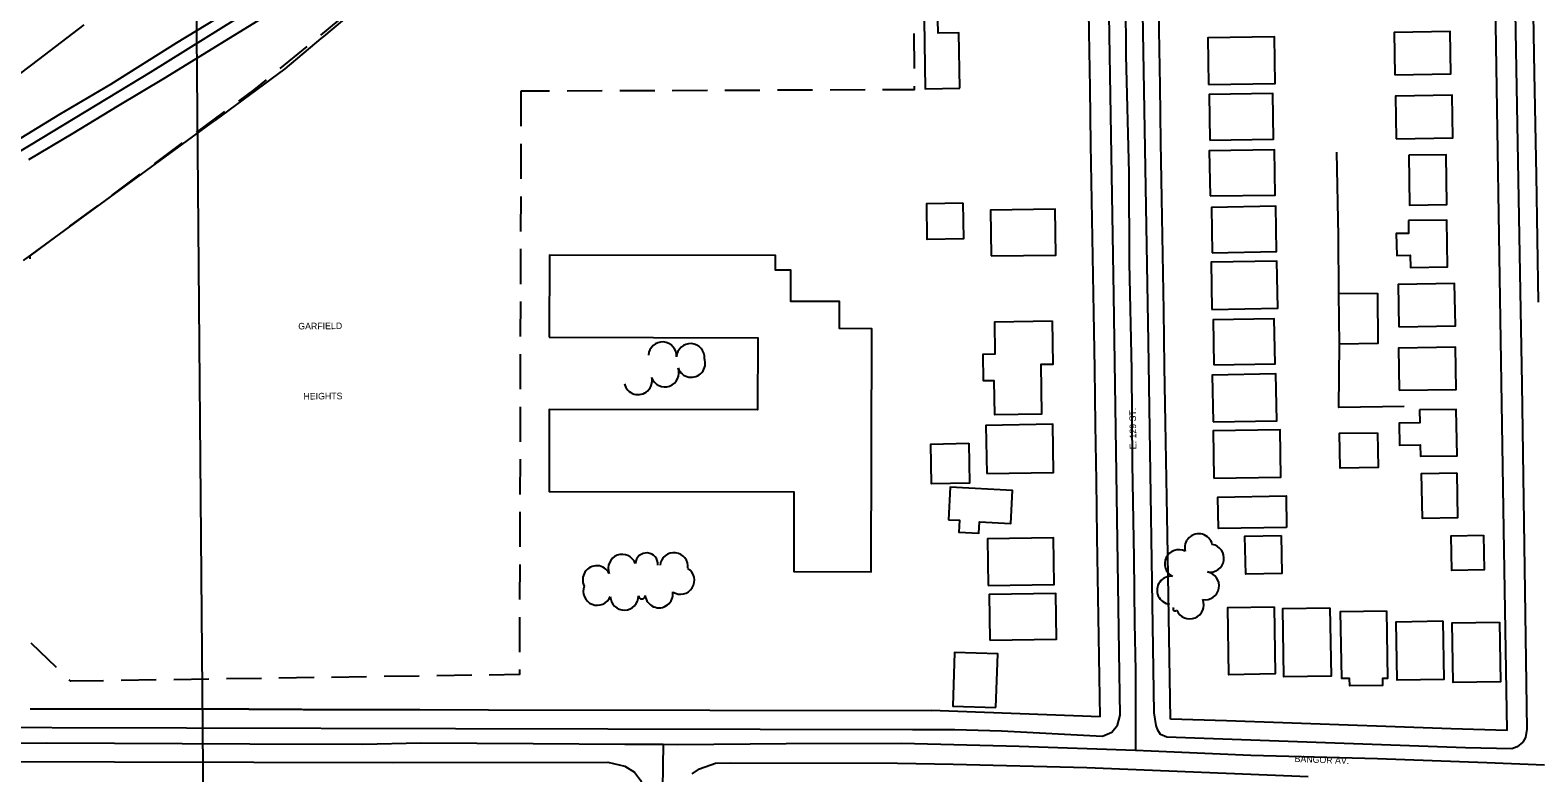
# Model space of a CAD drawing. Extents: x -2233 to 187241, y 4582 to 150524.
# Drawn here: x 112882 to 113957, y 58418 to 58948 of the extents above; entities that cross this region are included whole.
import ezdxf

# ---------------------------------------------------------------- set-up
doc = ezdxf.new("R2010")
doc.units = 0
for name, color, linetype in [('BLDG', 7, 'Continuous'), ('CITY-NAME', 7, 'Continuous'), ('GE_X_CL_2000', 7, 'Continuous'), ('GRID', 7, 'Continuous'), ('INTERSTATE', 7, 'Continuous'), ('RECREATION', 7, 'Continuous'), ('ROAD', 7, 'Continuous'), ('ROAD-NAME', 7, 'Continuous'), ('RW_X_Fee_RW', 7, 'Continuous'), ('TREES', 7, 'Continuous'), ('WALL', 7, 'Continuous')]:
    doc.layers.add(name, color=color, linetype=linetype)

msp = doc.modelspace()

# ---------------------------------------------------------------- linework, layer by layer
at = {"layer": 'BLDG'}
for points in [[(113545.3, 58906.3), (113544.6, 58945.7), (113529.8, 58945.5), (113529.6, 58955.3), (113533.1, 58955.4), (113532.8, 58971.8), (113519.5, 58971.6), (113520.6, 58905.9)], [(113722.6, 58908.8), (113770.2, 58909.6), (113769.6, 58943), (113722.1, 58942.2)], [(113855.4, 58915.9), (113895.5, 58916.6), (113895, 58946.6), (113854.9, 58945.9)], [(113723.6, 58869.3), (113769, 58870), (113768.5, 58902.5), (113723, 58901.8)], [(113856.4, 58870.2), (113896.7, 58870.9), (113896.3, 58901.3), (113856, 58900.6)], [(113723.7, 58829.4), (113770.2, 58830.1), (113769.7, 58862.4), (113723.1, 58861.6)], [(113865.4, 58858.4), (113866, 58822.9), (113892.6, 58823.4), (113892.1, 58858.8)], [(113547.5, 58824.4), (113547.9, 58798.8), (113522, 58798.4), (113521.6, 58824)], [(113725.1, 58788.9), (113771.1, 58789.7), (113770.6, 58822.1), (113724.6, 58821.3)], [(113567.5, 58786.6), (113613.8, 58787.3), (113613.2, 58820), (113567, 58819.2)], [(113865.1, 58811.8), (113865.2, 58802.7), (113856.5, 58802.6), (113856.8, 58786.9), (113866.5, 58787.1), (113866.6, 58778.5), (113893.1, 58778.9), (113892.6, 58812.2)], [(113252.5, 58728.7), (113401.1, 58728.3), (113400.9, 58676.8), (113252.4, 58677.2), (113252.3, 58618.7), (113426.9, 58618.3), (113426.8, 58561.5), (113482, 58561.4), (113482.4, 58734.7), (113459.4, 58734.8), (113459.5, 58754.1), (113424.7, 58754.2), (113424.8, 58776.6), (113413.8, 58776.6), (113413.9, 58786.9), (113252.6, 58787.3)], [(113725, 58748.5), (113771.9, 58749.3), (113771.3, 58783), (113724.5, 58782.2)], [(113843.1, 58760.2), (113843.4, 58724.1), (113815.9, 58723.8), (113815.6, 58759.9)], [(113858.3, 58736.1), (113898.6, 58736.8), (113898.1, 58766.9), (113857.8, 58766.2)], [(113611.1, 58740.4), (113611.6, 58709.3), (113602.9, 58709.2), (113603.5, 58673.8), (113570.1, 58673.3), (113569.7, 58697.6), (113562.1, 58697.5), (113561.8, 58716.6), (113570.4, 58716.8), (113570.1, 58739.7)], [(113726.4, 58709.1), (113770, 58709.8), (113769.5, 58741.8), (113725.9, 58741.1)], [(113858.6, 58690.8), (113899.2, 58691.5), (113898.7, 58721.5), (113858.1, 58720.8)], [(113725.9, 58668.4), (113771.2, 58669.1), (113770.6, 58702.5), (113725.3, 58701.7)], [(113873, 58676.8), (113873.2, 58667.6), (113858.6, 58667.4), (113858.8, 58651.6), (113873.6, 58651.9), (113873.7, 58643.8), (113899.8, 58644.2), (113899.2, 58677.2)], [(113564.5, 58631.5), (113612, 58632.2), (113611.5, 58666.6), (113563.9, 58665.8)], [(113726.4, 58628.1), (113774.2, 58628.9), (113773.7, 58662.6), (113725.8, 58661.8)], [(113551.7, 58653), (113552.1, 58624.7), (113525, 58624.2), (113524.6, 58652.5)], [(113843.2, 58660.6), (113843.6, 58635.8), (113816.4, 58635.4), (113816, 58660.2)], [(113899.6, 58632), (113900.1, 58599.8), (113875.1, 58599.4), (113874.5, 58631.6)], [(113537.1, 58598.5), (113544.9, 58598.1), (113544.5, 58589.7), (113558.8, 58589), (113559.2, 58597.1), (113581.5, 58595.9), (113582.7, 58619.4), (113538.3, 58621.7)], [(113778.2, 58593), (113729.7, 58592.2), (113729.3, 58614.7), (113777.9, 58615.5)], [(113565.5, 58551.5), (113612.5, 58552.3), (113612, 58585.7), (113564.9, 58585)], [(113774.4, 58587.3), (113774.8, 58560.2), (113749.1, 58559.8), (113748.6, 58586.8)], [(113918.7, 58587.5), (113919.2, 58562.8), (113896, 58562.4), (113895.6, 58587.1)], [(113566.7, 58512.7), (113614.1, 58513.4), (113613.6, 58545.9), (113566.1, 58545.1)], [(113769.3, 58536.4), (113770.1, 58488.5), (113737.1, 58488), (113736.3, 58535.9)], [(113809.2, 58535.6), (113810, 58486.9), (113776.3, 58486.4), (113775.5, 58535.1)], [(113849.5, 58533.6), (113850.3, 58485.3), (113846.6, 58485.2), (113846.7, 58480.4), (113823.3, 58480), (113823.2, 58485.3), (113817.6, 58485.2), (113816.8, 58533.1)], [(113889.7, 58526.3), (113890.4, 58484.6), (113857, 58484), (113856.3, 58525.7)], [(113930.2, 58525.5), (113930.9, 58483), (113897.1, 58482.5), (113896.4, 58524.9)], [(113570.9, 58464.5), (113572.3, 58502.8), (113541.5, 58503.9), (113540.2, 58465.6)]]:
    msp.add_lwpolyline(points, close=True, dxfattribs=at)
at = {"layer": 'GE_X_CL_2000'}
for points in [[(112322, 58601.6), (112419.7, 58626), (112454.6, 58640.3), (112483.9, 58654.7), (112549.4, 58686.8), (112613.3, 58718.6), (112690.6, 58758.2), (112748, 58787.7), (112812.7, 58824.1), (112883.1, 58866.1), (112968.1, 58917.7), (113054.4, 58971.6), (113150.6, 59034.2), (113253.8, 59104.1), (113362.9, 59177.7), (113450.8, 59237.6), (113520.2, 59286), (113597.8, 59341.2), (113697.9, 59412.2), (113699.5, 59413.3)], [(113663.2, 59007.7), (113663.6, 58929.6), (113665.7, 58846), (113666, 58781.5), (113667.6, 58705.4), (113668.2, 58638.3), (113669.3, 58571.1), (113669.9, 58524.8), (113670.4, 58491), (113670.4, 58434.1)], [(113953.6, 58986.9), (113954.8, 58917.1), (113956.2, 58844.1), (113957.7, 58753.7)], [(112737.3, 58439.8), (112758.3, 58439.9), (112819, 58438.9), (112894.1, 58439.5), (113038.9, 58438.6), (113119.5, 58438.4), (113160.7, 58439.4), (113241.1, 58439), (113306.4, 58438.5), (113333.7, 58438.4)], [(113333.7, 58438.4), (113332.8, 58374.7), (113332.3, 58298.8), (113332.4, 58211.5), (113331.5, 58143.3), (113331.1, 58090.5)], [(113333.7, 58438.4), (113344.1, 58438.3), (113421.4, 58438.9), (113503.6, 58439.1), (113587.6, 58437.1), (113670.4, 58434.1)], [(113670.4, 58434.1), (113681.8, 58433.7), (113752.7, 58430.5), (113843, 58428.3), (113921.1, 58425.4), (113962.3, 58423.6)]]:
    msp.add_lwpolyline(points, dxfattribs=at)
at = {"layer": 'GRID'}
msp.add_line((112991, 60069.8), (113014.5, 57372.1), dxfattribs=at)
at = {"layer": 'INTERSTATE'}
for points in [[(112854.6, 58901.4), (112888.4, 58926.8), (112920.8, 58951.4)], [(113022, 58960), (112986.4, 58938.4), (112939.5, 58909), (112903.3, 58887.4), (112864.1, 58863.6)], [(112881.3, 58855.4), (112912.9, 58874.3), (112944.5, 58893.4), (112978.7, 58913.9), (113011.6, 58934.1), (113047.9, 58956.4)]]:
    msp.add_lwpolyline(points, dxfattribs=at)
at = {"layer": 'RECREATION'}
for p, q in [((113089.5, 58944.1), (113108.9, 58959.9)), ((113512.5, 58945.2), (113512.6, 58920.2)), ((113060.5, 58920.3), (113079.9, 58936.1)), ((113232.3, 58904.1), (113232.2, 58879.1)), ((113252.7, 58904.1), (113232.3, 58904.1)), ((113290.2, 58904.3), (113265.2, 58904.2)), ((113327.7, 58904.4), (113302.7, 58904.3)), ((113365.2, 58904.6), (113340.2, 58904.5)), ((113402.7, 58904.7), (113377.7, 58904.6)), ((113440.2, 58904.9), (113415.2, 58904.8)), ((113477.7, 58905), (113452.7, 58904.9)), ((113001, 58874.7), (113021.1, 58889.6)), ((112970.9, 58852.4), (112991, 58867.3)), ((113232.2, 58866.6), (113232.1, 58841.6)), ((112940.7, 58830.1), (112960.8, 58844.9)), ((112910.6, 58807.8), (112930.7, 58822.6)), ((113232.1, 58829.1), (113232, 58804.1)), ((113232, 58791.6), (113231.9, 58766.6)), ((113231.9, 58754.1), (113231.8, 58729.1)), ((113231.8, 58716.6), (113231.7, 58691.6)), ((113231.7, 58679.1), (113231.6, 58654.1)), ((113231.6, 58641.6), (113231.5, 58616.6)), ((113231.5, 58604.1), (113231.4, 58579.1)), ((113231.4, 58566.6), (113231.3, 58541.6)), ((113231.3, 58529.1), (113231.2, 58504.1)), ((112901.1, 58493.1), (112883.1, 58510.4)), ((112972.2, 58484.3), (112947.2, 58483.9)), ((113009.7, 58484.8), (112984.7, 58484.4)), ((113047.2, 58485.4), (113022.2, 58485)), ((113084.7, 58485.9), (113059.7, 58485.5)), ((113122.2, 58486.5), (113097.2, 58486.1)), ((113159.7, 58487), (113134.7, 58486.6)), ((113197.2, 58487.6), (113172.2, 58487.2))]:
    msp.add_line(p, q, dxfattribs=at)
for points in [[(113031.1, 58897), (113042, 58905.1), (113050.9, 58912.3)], [(113512.6, 58907.7), (113512.6, 58905.2), (113490.2, 58905.1)], [(112882.3, 58784.5), (112882.3, 58786.8), (112900.5, 58800.3)], [(113231.2, 58491.6), (113231.2, 58488.1), (113209.7, 58487.7)], [(112934.7, 58483.7), (112911.3, 58483.3), (112910.2, 58484.4)]]:
    msp.add_lwpolyline(points, dxfattribs=at)
at = {"layer": 'ROAD'}
for points in [[(113940.6, 59000), (113946, 58695.1), (113949.6, 58449.2), (113948.7, 58443.1), (113946.7, 58439.8), (113942.8, 58436.5), (113938.9, 58435.2), (113905.8, 58435.8), (113692.8, 58443.4), (113688.3, 58445.4), (113686.4, 58448.4), (113685.3, 58451.8), (113683.9, 58460.8), (113679.8, 58725.1), (113673.6, 59084.4)], [(112801.6, 58450.6), (113185.5, 58449.6), (113511.4, 58448.8), (113541.6, 58448.9), (113575, 58447.9), (113646.9, 58444.2), (113653.6, 58447), (113657.7, 58452.1), (113659.7, 58459.1), (113658.9, 58504.4), (113655, 58758.6), (113651.2, 58987.3)], [(112496.6, 58425.5), (112842.7, 58426.1), (113141.4, 58425.4), (113294.2, 58425.6), (113306.3, 58422.7), (113313.3, 58418.5), (113317.5, 58412.7), (113320, 58407), (113320.7, 58399.9), (113321.3, 58389.1), (113319.3, 58112.7), (113316.8, 58107.4), (113313.3, 58104.3), (113307.4, 58101.9), (113293.1, 58101.5), (112776.8, 58106), (112495.1, 58107.7)], [(113354.3, 58417.2), (113359.7, 58420.8), (113371.1, 58425), (113381.8, 58425.1), (113500.7, 58425), (113540.5, 58424.3), (113635.9, 58421.7), (113793.7, 58415.5)]]:
    msp.add_lwpolyline(points, dxfattribs=at)
at = {"layer": 'RW_X_Fee_RW'}
for p, q in [((113063.9, 58920), (113013.9, 58883.3)), ((113645.4, 58458), (113524.9, 58462.4))]:
    msp.add_line(p, q, dxfattribs=at)
for points in [[(113935.6, 58448.1), (113933.3, 58591.5), (113932.5, 58636.5), (113931.8, 58681.5), (113931.1, 58726.5), (113930.3, 58771.5), (113929.6, 58816.5), (113928.9, 58861.5), (113928.1, 58906.5), (113927.4, 58951.5), (113926.7, 58996.5), (113925.9, 59041.5), (113925.2, 59086.5), (113924.5, 59131.5), (113923.7, 59176.5), (113923, 59221.5), (113922.8, 59231.4), (113922.2, 59271.4), (113921.5, 59311.4), (113920.9, 59351.4), (113920.2, 59391.4)], [(113645.4, 58458), (113643.3, 58586.2), (113642.7, 58626.2), (113642, 58666.2), (113641.4, 58706.2), (113640.7, 58746.2), (113640, 58786.2), (113639.4, 58826.2), (113638.7, 58866.2), (113638.1, 58906.2), (113637.4, 58946.2), (113637.2, 58961.2), (113636.8, 58986.2), (113636.1, 59026.1), (113635.5, 59066.1), (113634.8, 59106.1), (113634.2, 59146.1), (113633.5, 59186.1), (113632.9, 59226.1), (113632.2, 59266.1), (113631.6, 59306.1)], [(113695.4, 58456.3), (113693.3, 58587.8), (113692.6, 58627.7), (113692, 58667.7), (113691.3, 58707.7), (113690.7, 58747.7), (113690, 58787.7), (113689.4, 58827.7), (113688.7, 58867.7), (113688.1, 58907.7), (113687.4, 58947.7), (113686.8, 58987.7), (113686.1, 59027.7), (113685.5, 59067.7), (113684.8, 59107.7), (113684.2, 59147.7), (113683.5, 59187.7), (113682.8, 59227.7), (113682.2, 59267.7), (113682.1, 59272.5), (113681.5, 59307.7)], [(113186.1, 59022.9), (113150.7, 58993.1), (113091.5, 58943.2), (113089.6, 58941.6), (113063.9, 58920)], [(112877.6, 58783.5), (112945.7, 58833.4), (113013.9, 58883.3)], [(113038.3, 58463.3), (113000.9, 58463.4), (112999.6, 58463.3), (112998.3, 58463.3), (112962.2, 58463.4), (112912.2, 58463.4), (112882.2, 58463.5)], [(113038.3, 58463.3), (113075.7, 58463.3), (113077, 58463.2), (113078.3, 58463.2), (113111.2, 58463.2), (113160.2, 58463.1), (113209.2, 58463), (113524.9, 58462.4)], [(113935.6, 58448.1), (113895.6, 58449.5), (113855.6, 58450.9), (113815.5, 58452.2), (113775.5, 58453.6), (113735.5, 58455), (113695.4, 58456.3)]]:
    msp.add_lwpolyline(points, dxfattribs=at)
at = {"layer": 'TREES'}
for centre, radius, start, end in [((113333.2, 58715.3), 10, 356.4474, 176.4474), ((113353.2, 58714.1), 10, 356.4474, 176.4474), ((113334.9, 58703.3), 10, 199.6797, 19.6797), ((113353.7, 58710.1), 10, 199.6841, 19.6841), ((113315.8, 58697.7), 9.99, 193.3901, 13.3901), ((113715.6, 58578.5), 10, 14.2896, 194.2896), ((113321.9, 58566.8), 8.05, 355.8726, 175.8726), ((113341.4, 58565), 10, 353.489, 173.489), ((113701.4, 58567.1), 10, 63.5725, 243.5725), ((113723.6, 58571.1), 10, 260.2995, 80.2995), ((113286.3, 58555.7), 10, 26.8204, 206.8204), ((113304.5, 58563.8), 10, 21.0655, 201.0655), ((113346, 58555.4), 10, 237.5284, 57.5284), ((113695.9, 58548.2), 10, 84.1093, 264.1093), ((113720.2, 58551.4), 10, 260.0806, 80.0806), ((113286.7, 58547.5), 10, 158.5244, 338.5244), ((113306, 58544.1), 10, 181.3137, 1.3137), ((113318.4, 58544.4), 2.39, 181.3137, 1.3137), ((113330.7, 58545.7), 10, 187.3442, 7.3442), ((113698.8, 58534.9), 1.47, 140.0255, 320.0255), ((113709.2, 58537.8), 10, 202.3389, 22.3389)]:
    msp.add_arc(centre, radius, start, end, dxfattribs=at)
at = {"layer": 'WALL'}
for points in [[(113815.6, 58759.9), (113815.2, 58800.8), (113814, 58860.6)], [(113862, 58679.3), (113815.6, 58678.6), (113815.9, 58723.8)]]:
    msp.add_lwpolyline(points, dxfattribs=at)

# ---------------------------------------------------------------- texts
at = {"layer": 'CITY-NAME'}
for s, p in [('GARFIELD', (113073.5, 58734.2)), ('HEIGHTS', (113077.2, 58684.2))]:
    msp.add_text(s, height=4.68, rotation=0.5, dxfattribs=at).set_placement(p)
at = {"layer": 'ROAD-NAME'}
for s, rotation, p in [('E. 129 ST.', 90.5, (113671.1, 58648.8)), ('BANGOR AV.', 357.9568, (113783.9, 58425.7))]:
    msp.add_text(s, height=4.68, rotation=rotation, dxfattribs=at).set_placement(p)

doc.saveas('drawing.dxf')
